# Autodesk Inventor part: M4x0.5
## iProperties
IsCustomPart: 1
Company: 한국ATC센터
Created: 2009-02
Part Number: M4x0.5
Material: 강, 연강
Description: 6각머리 태핑 나사
Document SubType Name: Modeling
Standard: KS B 1003
Designer: KYOUNG IL JANG
Standards Organization: KS
Language: ko-KR
Size Designation: M 4 x 12
Categories: <MemberInstance><Categories><Category DisplayName="조임쇠" InternalName="e4da775c-781d-43d5-af7c-5136215cf5a6" Mnemonic="FSTN"><Category DisplayName="볼트" InternalN
Density: 1 g/cm^3
Author: KYOUNG IL JANG
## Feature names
1. Fillet2
